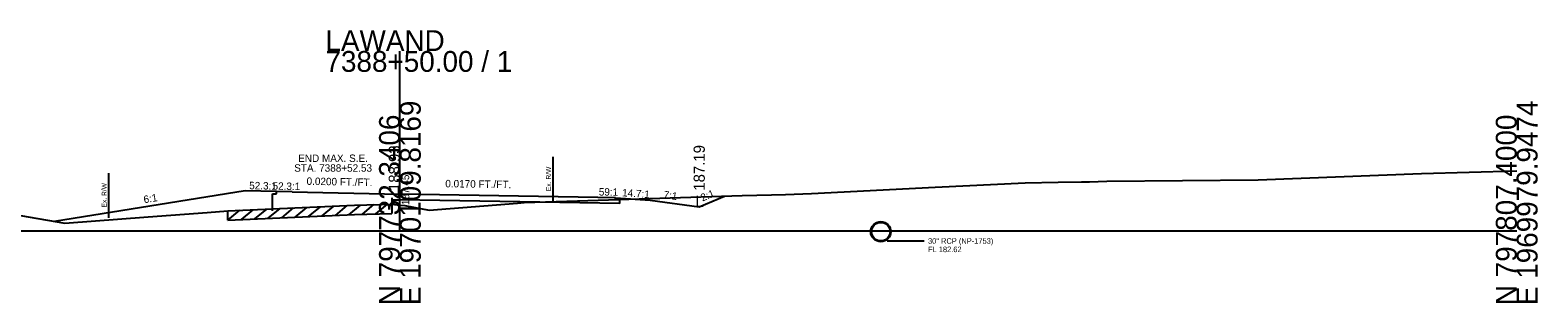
# Model space of a CAD drawing. Extents: x -26 to 303, y -10 to 1532.
# Drawn here: x 100.3 to 302.8, y 990.3 to 1027 of the extents above; entities that cross this region are included whole.
import ezdxf

# ---------------------------------------------------------------- set-up
doc = ezdxf.new("R2010")
doc.units = 0
for name, color, linetype in [('RD_GPK_XS_Cell', 7, 'Continuous'), ('RD_XS_Base', 7, 'Continuous'), ('RD_XS_EarthShd', 7, 'Continuous'), ('RD_XS_ExGround', 7, 'Continuous'), ('RD_XS_ExPaveRet', 7, 'Continuous'), ('RD_XS_ExRW', 7, 'Continuous'), ('RD_XS_Misc_Line', 7, 'Continuous'), ('RD_XS_Pave', 7, 'Continuous'), ('RD_XS_PaveOvlay', 7, 'Continuous'), ('RD_XS_PaveShd', 7, 'Continuous'), ('RD_XS_Pipe', 7, 'Continuous'), ('RD_XS_TieSlope', 7, 'Continuous'), ('RD_XS_TX_Elev_EX', 7, 'Continuous'), ('RD_XS_TX_Elev_PR', 7, 'Continuous'), ('RD_XS_TX_Misc', 7, 'Continuous'), ('RD_XS_TX_MkPT', 7, 'Continuous'), ('RD_XS_TX_Notes', 7, 'Continuous'), ('RD_XS_TX_Profile', 7, 'Continuous'), ('RD_XS_TX_ShdSlope', 7, 'Continuous'), ('RD_XS_TX_Slope', 7, 'Continuous')]:
    doc.layers.add(name, color=color, linetype=linetype)

msp = doc.modelspace()

# ---------------------------------------------------------------- linework, layer by layer
at = {"layer": 'RD_GPK_XS_Cell'}
for p, q in [((150, 1000), (150, 1024.15)), ((0, 1000), (150, 1000)), ((150, 1000), (300, 1000))]:
    msp.add_line(p, q, dxfattribs=at)
at = {"layer": 'RD_XS_Base'}
for p, q in [((132.89, 1004.97), (133.41, 1004.96)), ((132.89, 1002.67), (132.89, 1004.97)), ((133.41, 1004.96), (133.41, 1005.26)), ((178.94, 1004.14), (178.94, 1004.44)), ((148.9, 1004.17), (150, 1004.15)), ((179.52, 1003.65), (150, 1004.15)), ((179.52, 1004.14), (178.94, 1004.14)), ((179.52, 1003.65), (179.52, 1004.13))]:
    msp.add_line(p, q, dxfattribs=at)
at = {"layer": 'RD_XS_EarthShd'}
for p, q in [((133.41, 1005.26), (129.23, 1005.34)), ((178.94, 1004.44), (183.63, 1004.12))]:
    msp.add_line(p, q, dxfattribs=at)
at = {"layer": 'RD_XS_ExGround'}
msp.add_lwpolyline([(99.04, 1002.05), (104.99, 1001.03), (116.19, 1001.85), (124.13, 1002.45), (126.91, 1002.68), (143.89, 1003.42), (148.9, 1003.58), (150, 1003.45), (150.64, 1003.37), (153.94, 1002.76), (165.81, 1003.69), (166.68, 1003.79), (173.87, 1004.02), (195.98, 1004.72), (199.93, 1004.81), (201.79, 1004.87), (205.28, 1005.02), (221.89, 1005.87), (233.98, 1006.42), (238.42, 1006.51), (241.55, 1006.59), (242.64, 1006.59), (244.93, 1006.64), (265.29, 1006.86), (287.22, 1007.71), (300, 1008.05)], dxfattribs=at)
at = {"layer": 'RD_XS_ExPaveRet'}
for p, q in [((126.91, 1001.43), (126.91, 1002.68)), ((148.9, 1003.58), (148.9, 1002.33)), ((126.91, 1001.43), (143.89, 1002.17)), ((143.89, 1002.17), (148.9, 1002.33))]:
    msp.add_line(p, q, dxfattribs=at)
at = {"layer": 'RD_XS_ExRW'}
for p, q in [((170.54, 1009.93), (170.54, 1003.93)), ((110.85, 1007.73), (110.85, 1001.73))]:
    msp.add_line(p, q, dxfattribs=at)
at = {"layer": 'RD_XS_Misc_Line'}
for p, q in [((126.91, 1001.43), (128.5, 1002.75)), ((128.72, 1001.51), (130.3, 1002.83)), ((130.52, 1001.59), (132.11, 1002.91)), ((132.32, 1001.67), (133.91, 1002.99)), ((134.13, 1001.75), (135.72, 1003.07)), ((135.93, 1001.83), (137.52, 1003.14)), ((137.74, 1001.9), (139.33, 1003.22)), ((139.54, 1001.98), (141.13, 1003.3)), ((141.35, 1002.06), (142.93, 1003.38)), ((143.15, 1002.14), (144.73, 1003.45)), ((144.96, 1002.21), (146.52, 1003.51)), ((146.76, 1002.26), (148.33, 1003.56))]:
    msp.add_line(p, q, dxfattribs=at)
at = {"layer": 'RD_XS_Pave'}
for p in [(135.51, 1005.22), (176.59, 1004.48)]:
    msp.add_line(p, (150, 1004.93), dxfattribs=at)
at = {"layer": 'RD_XS_PaveOvlay'}
for p, q in [((148.9, 1004.44), (148.9, 1003.58)), ((132.89, 1002.94), (143.89, 1003.42)), ((143.89, 1003.42), (148.9, 1003.58))]:
    msp.add_line(p, q, dxfattribs=at)
at = {"layer": 'RD_XS_PaveShd'}
for p, q in [((135.51, 1005.22), (133.41, 1005.26)), ((178.94, 1004.44), (176.59, 1004.48))]:
    msp.add_line(p, q, dxfattribs=at)
at = {"layer": 'RD_XS_Pipe'}
msp.add_line((215.43, 998.62), (220.43, 998.62), dxfattribs=at)
for radius in [1.35, 1.25]:
    msp.add_circle((214.59, 999.87), radius, dxfattribs=at)
at = {"layer": 'RD_XS_TieSlope'}
for p, q in [((129.23, 1005.34), (103.62, 1001.26)), ((190.2, 1003.19), (193.61, 1004.64)), ((183.63, 1004.12), (190.2, 1003.19))]:
    msp.add_line(p, q, dxfattribs=at)

# ---------------------------------------------------------------- texts
at = {"layer": 'RD_GPK_XS_Cell'}
for s, p in [('LAWAND', (140, 1024.15)), ('7388+50.00 / 1', (140, 1021.35))]:
    msp.add_text(s, height=2.8, dxfattribs=at).set_placement(p)
for s, p in [('E 1970109.8169', (152.8, 990)), ('E 1969979.9474', (302.8, 990)), ('N 797732.3406', (150, 990)), ('N 797807.4000', (300, 990))]:
    msp.add_text(s, height=2.8, rotation=90, dxfattribs=at).set_placement(p)
at = {"layer": 'RD_XS_ExRW'}
for p in [(170.29, 1005.32), (110.6, 1003.12)]:
    msp.add_text('Ex. R/W ', height=0.65, rotation=90, dxfattribs=at).set_placement(p)
at = {"layer": 'RD_XS_Pipe'}
for s, p in [('30" RCP (NP-1753)', (220.93, 998.25)), ('FL 182.62', (220.93, 997.12))]:
    msp.add_text(s, height=0.75, dxfattribs=at).set_placement(p)
at = {"layer": 'RD_XS_TX_Elev_EX'}
msp.add_text('187.45', height=1, rotation=90, dxfattribs=at).set_placement((151.25, 1003.45))
at = {"layer": 'RD_XS_TX_Elev_PR'}
msp.add_text('188.93', height=1.5, rotation=90, dxfattribs=at).set_placement((150, 1005.33))
at = {"layer": 'RD_XS_TX_Misc'}
msp.add_text('187.19', height=1.5, rotation=90, dxfattribs=at).set_placement((190.95, 1005.38))
at = {"layer": 'RD_XS_TX_MkPT'}
msp.add_text('L', height=1.5, dxfattribs=at).set_placement((189.7, 1003.19))
at = {"layer": 'RD_XS_TX_Notes'}
for s, p in [('STA. 7388+52.53', (135.81, 1007.93)), ('END MAX. S.E.', (136.34, 1009.24))]:
    msp.add_text(s, height=1, dxfattribs=at).set_placement(p)
at = {"layer": 'RD_XS_TX_Profile'}
for s, rotation, p in [('52.3:1', 358.9053, (132.89, 1005.52)), ('59:1', 359.1691, (176.71, 1004.73))]:
    msp.add_text(s, height=1, rotation=rotation, dxfattribs=at).set_placement(p)
at = {"layer": 'RD_XS_TX_ShdSlope'}
for s, rotation, p in [('52.3:1', 358.9053, (129.75, 1005.58)), ('14.7:1', 356.0997, (179.82, 1004.63))]:
    msp.add_text(s, height=1, rotation=rotation, dxfattribs=at).set_placement(p)
at = {"layer": 'RD_XS_TX_Slope'}
for s, rotation, p in [('0.0200 FT./FT.', 358.9053, (137.46, 1006.17)), ('0.0170 FT./FT.', 359.1691, (156.09, 1005.84)), ('6:1', 9.0477, (115.65, 1003.69)), ('7:1', 351.9159, (185.35, 1004.38)), ('2:1', 23.0795, (190.65, 1003.92))]:
    msp.add_text(s, height=1, rotation=rotation, dxfattribs=at).set_placement(p)

doc.saveas('drawing.dxf')
